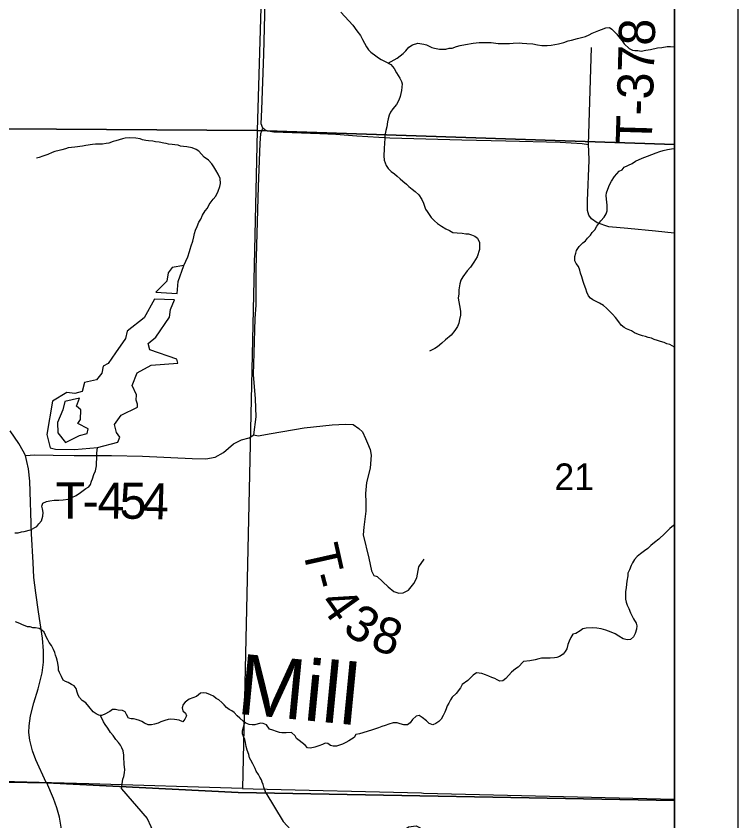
# Model space of a CAD drawing. Extents: x 0 to 34, y 0 to 22.
# Drawn here: x 29.781 to 30.917, y 17.785 to 19.051 of the extents above; entities that cross this region are included whole.
import ezdxf

# ---------------------------------------------------------------- set-up
doc = ezdxf.new("R2010")
doc.units = 0
for name, color, linetype in [('GM_X_Adjacent_County', 7, 'Continuous'), ('GM_X_County', 7, 'Continuous'), ('GM_X_County_Road', 7, 'Continuous'), ('GM_X_Minor_Lake', 7, 'Continuous'), ('GM_X_Minor_River', 7, 'Continuous'), ('GM_X_Minor_River_Text', 7, 'Continuous'), ('GM_X_Section', 7, 'Continuous'), ('GM_X_Section_Text', 7, 'Continuous'), ('GM_X_State_Route', 7, 'Continuous'), ('GM_X_Township', 7, 'Continuous'), ('GM_X_Township_Road', 7, 'Continuous'), ('GM_X_Township_Road_Text', 7, 'Continuous'), ('SH_Data', 7, 'Continuous')]:
    doc.layers.add(name, color=color, linetype=linetype)

msp = doc.modelspace()

# ---------------------------------------------------------------- linework, layer by layer
at = {"layer": 'GM_X_Adjacent_County'}
for points in [[(30.8167, 17.8174), (30.8167, 20.9), (24.0167, 20.9), (24.0167, 18.0693)], [(24.0167, 18.0693), (24.0167, 14.1), (30.8167, 14.1), (30.8167, 17.8174)], [(30.8167, 17.8174), (30.1304, 17.8301), (29.8296, 17.8449), (29.1279, 17.8574), (28.6324, 17.8677)], [(28.6324, 17.8677), (29.1279, 17.8574), (29.8296, 17.8449), (30.1304, 17.8301), (30.8167, 17.8174)]]:
    msp.add_lwpolyline(points, dxfattribs=at)
at = {"layer": 'GM_X_County'}
for points in [[(30.8167, 17.8174), (30.8167, 20.9), (24.0167, 20.9), (24.0167, 18.0693)], [(24.0167, 18.0693), (24.0167, 14.1), (30.8167, 14.1), (30.8167, 17.8174)], [(28.6324, 17.8677), (29.1279, 17.8574), (29.8296, 17.8449), (30.1304, 17.8301), (30.8167, 17.8174)], [(30.8167, 17.8174), (30.1304, 17.8301), (29.8296, 17.8449), (29.1279, 17.8574), (28.6324, 17.8677)]]:
    msp.add_lwpolyline(points, dxfattribs=at)
at = {"layer": 'GM_X_County_Road'}
for points in [[(30.1693, 18.8745), (30.167, 18.8813), (30.1678, 18.9036), (30.1709, 18.9907), (30.1749, 19.1352), (30.1785, 19.2629), (30.1788, 19.2864), (30.1782, 19.3154), (30.1794, 19.3235), (30.1825, 19.3315), (30.1887, 19.3469)], [(30.8167, 18.7092), (30.8162, 18.7094), (30.7869, 18.7126), (30.7433, 18.7167), (30.7139, 18.7195), (30.6955, 18.7258), (30.6866, 18.7321), (30.6823, 18.7377), (30.6803, 18.7451), (30.6803, 18.7603), (30.6825, 18.8243), (30.6823, 18.8382), (30.6818, 18.8484), (30.6719, 18.8496), (30.637, 18.8519), (30.5516, 18.8539), (30.4823, 18.8557), (30.3691, 18.8587), (30.3172, 18.862), (30.2842, 18.8646), (30.2589, 18.8656), (30.1865, 18.8681), (30.1746, 18.8704), (30.1693, 18.8745)]]:
    msp.add_lwpolyline(points, dxfattribs=at)
at = {"layer": 'GM_X_Minor_Lake'}
for points in [[(30.0453, 18.6586), (30.0268, 18.6555), (30.0204, 18.6472), (30.0185, 18.6339), (30.0011, 18.6168), (30.0345, 18.6146)], [(30.0345, 18.6146), (30.0363, 18.6332), (30.0453, 18.6586)], [(29.9989, 18.6058), (29.9827, 18.5762), (29.9558, 18.5552), (29.9536, 18.5435), (29.9378, 18.5214), (29.9261, 18.5043), (29.9181, 18.5005), (29.9162, 18.4891), (29.9076, 18.4789), (29.889, 18.4747), (29.8853, 18.4606), (29.8735, 18.4572), (29.861, 18.4591), (29.8387, 18.445), (29.8298, 18.393), (29.8347, 18.3721), (29.8435, 18.3695), (29.873, 18.3692), (29.9094, 18.3723)], [(29.9094, 18.3723), (29.9416, 18.3807), (29.9446, 18.3887), (29.9393, 18.3959), (29.9362, 18.4088), (29.9468, 18.4232), (29.9721, 18.4358), (29.9725, 18.4403), (29.9702, 18.4468), (29.9705, 18.4551), (29.9637, 18.4699), (29.9719, 18.4896), (29.9939, 18.5018), (30.0359, 18.505), (30.0344, 18.5114), (29.9919, 18.5257), (29.9892, 18.536), (30.0013, 18.5458), (30.0228, 18.5774), (30.024, 18.5891), (30.0307, 18.6047), (29.9989, 18.6058)], [(29.8811, 18.45), (29.858, 18.4446), (29.855, 18.4314), (29.8467, 18.4116), (29.8472, 18.3953), (29.859, 18.3805)], [(29.859, 18.3805), (29.8813, 18.3912), (29.8934, 18.3946), (29.8945, 18.4019), (29.8786, 18.4102), (29.8824, 18.4166), (29.8831, 18.4314), (29.8762, 18.4375), (29.8811, 18.45)]]:
    msp.add_lwpolyline(points, dxfattribs=at)
at = {"layer": 'GM_X_Minor_River'}
for points in [[(30.292, 19.0569), (30.2984, 19.0501), (30.3045, 19.0433), (30.311, 19.0365), (30.3175, 19.0274), (30.3228, 19.0202), (30.3262, 19.0138), (30.3323, 19.0024), (30.3357, 18.9975), (30.3395, 18.9941), (30.3471, 18.9884), (30.3513, 18.985), (30.3555, 18.9824), (30.3597, 18.9805), (30.3638, 18.9782), (30.3707, 18.9748), (30.376, 18.9684), (30.3798, 18.9616), (30.3851, 18.9532), (30.3874, 18.9479), (30.3886, 18.9441), (30.3878, 18.9335), (30.3856, 18.924), (30.3833, 18.9183), (30.3796, 18.9115), (30.3739, 18.905)], [(30.3666, 18.9769), (30.3809, 18.9843), (30.3903, 18.9919), (30.3945, 18.9961), (30.399, 19.0018), (30.4047, 19.0056), (30.4134, 19.0083), (30.4225, 19.0064), (30.427, 19.0053), (30.4354, 19.0015), (30.4396, 19.0004), (30.4471, 18.9989), (30.4574, 18.9989), (30.4623, 19), (30.4672, 19.0004), (30.474, 19.0027), (30.4797, 19.0046), (30.488, 19.0062), (30.5005, 19.0081), (30.5096, 19.0089), (30.5286, 19.0089), (30.5396, 19.0078), (30.5574, 19.0078), (30.5631, 19.0082), (30.5729, 19.0086), (30.5775, 19.0082), (30.5847, 19.0075), (30.5941, 19.0068), (30.6017, 19.0053), (30.6085, 19.0045), (30.6169, 19.0045), (30.6229, 19.0049), (30.6343, 19.0068), (30.643, 19.0091), (30.6498, 19.0118), (30.6551, 19.0129), (30.6646, 19.0156), (30.6767, 19.0187), (30.6828, 19.0213), (30.6873, 19.0236), (30.6979, 19.0282), (30.7021, 19.0297), (30.7089, 19.0324), (30.7146, 19.0328), (30.7184, 19.0301), (30.7222, 19.0267), (30.7263, 19.0222), (30.7286, 19.0184), (30.7347, 19.0116), (30.7378, 19.0071), (30.7457, 18.9995), (30.7507, 18.9972), (30.7545, 18.9965), (30.7594, 18.9965), (30.7647, 18.9957), (30.7719, 18.9973), (30.7791, 18.9984), (30.7901, 19.0007), (30.7969, 19.0015), (30.8056, 19.0026), (30.8105, 19.0027), (30.8167, 19.0023)], [(30.3739, 18.905), (30.3705, 18.8997), (30.3683, 18.8948), (30.3668, 18.8891), (30.3656, 18.8842), (30.3645, 18.8766), (30.363, 18.8709), (30.3615, 18.8629), (30.3612, 18.8576), (30.3608, 18.8515), (30.3601, 18.8417), (30.3597, 18.8307), (30.3605, 18.8239), (30.3617, 18.8201), (30.3636, 18.8155), (30.3666, 18.811), (30.3712, 18.8064), (30.3765, 18.8027), (30.3807, 18.7989), (30.3852, 18.7947), (30.3898, 18.7909), (30.3955, 18.7864), (30.3993, 18.7826), (30.4042, 18.7788), (30.4092, 18.7747), (30.4149, 18.7694), (30.4194, 18.7622), (30.4221, 18.7565), (30.4236, 18.7516), (30.4255, 18.747), (30.4278, 18.7432), (30.4343, 18.7338), (30.4396, 18.7288), (30.4442, 18.7247), (30.4502, 18.7205), (30.4571, 18.7164), (30.4631, 18.7133), (30.4685, 18.7103), (30.4753, 18.7099), (30.4829, 18.7092), (30.4889, 18.7085), (30.4931, 18.7081), (30.4977, 18.7066), (30.503, 18.7047), (30.5071, 18.7013), (30.5102, 18.6948), (30.5102, 18.6835), (30.5065, 18.6721), (30.5012, 18.6637), (30.4963, 18.6561), (30.4906, 18.6504), (30.4838, 18.6406), (30.4808, 18.6356), (30.4793, 18.6295), (30.4778, 18.6201), (30.4775, 18.614), (30.4767, 18.6072), (30.4787, 18.5954), (30.4806, 18.5867), (30.4802, 18.5806), (30.4787, 18.5738), (30.4776, 18.5681), (30.4757, 18.5624), (30.4716, 18.5563), (30.4655, 18.5491), (30.4568, 18.5419), (30.4508, 18.5366), (30.4444, 18.5308), (30.4398, 18.5278), (30.4315, 18.5236)], [(30.0453, 18.6586), (30.0517, 18.6723), (30.054, 18.6806), (30.0551, 18.6844), (30.0566, 18.6893), (30.0592, 18.6969), (30.0611, 18.7038), (30.0622, 18.7087), (30.0637, 18.714), (30.0664, 18.7201), (30.0686, 18.7265), (30.0717, 18.7315), (30.0743, 18.7379), (30.0788, 18.7444), (30.0822, 18.7489), (30.0852, 18.7543), (30.0882, 18.7584), (30.0913, 18.763), (30.0954, 18.7676), (30.0992, 18.7755), (30.1018, 18.7827), (30.1026, 18.7873), (30.1022, 18.7953), (30.0991, 18.8021), (30.0957, 18.8085), (30.0922, 18.8138), (30.0892, 18.8184), (30.0839, 18.824), (30.077, 18.829), (30.0729, 18.8335), (30.0687, 18.8384), (30.0645, 18.8411), (30.0581, 18.8437), (30.0501, 18.8452), (30.0444, 18.8456), (30.0402, 18.8463), (30.0364, 18.8478), (30.0308, 18.8482), (30.0266, 18.8489), (30.0213, 18.8493), (30.0175, 18.8504), (30.0137, 18.8508), (30.0065, 18.8523), (30.0004, 18.8531), (29.9966, 18.8538), (29.9894, 18.8546), (29.9853, 18.8553), (29.9803, 18.8561), (29.9765, 18.8576), (29.9697, 18.8587), (29.9602, 18.859), (29.953, 18.8586), (29.9489, 18.8575), (29.9383, 18.8544), (29.9341, 18.8537), (29.9273, 18.851), (29.9231, 18.8506), (29.9171, 18.8495), (29.9061, 18.8491), (29.9015, 18.8487), (29.8909, 18.8471), (29.8856, 18.8464), (29.8735, 18.8444), (29.8633, 18.8433), (29.8591, 18.8421), (29.8534, 18.8402), (29.8493, 18.8395), (29.8421, 18.8376), (29.8379, 18.836), (29.8315, 18.833), (29.8232, 18.8303), (29.8179, 18.8284), (29.8137, 18.8273)], [(30.7176, 18.7909), (30.7228, 18.7984), (30.73, 18.8068), (30.7346, 18.8091), (30.738, 18.8129), (30.7504, 18.819), (30.7557, 18.8228), (30.7663, 18.8274), (30.7747, 18.8304), (30.7883, 18.8358), (30.794, 18.8377), (30.7993, 18.8396), (30.8061, 18.8411), (30.8121, 18.8422), (30.8167, 18.8423)], [(30.8167, 18.53), (30.8134, 18.532), (30.8096, 18.5343), (30.8047, 18.5354), (30.8005, 18.5377), (30.7949, 18.5388), (30.7903, 18.5407), (30.785, 18.5422), (30.7808, 18.5441), (30.7755, 18.5452), (30.7713, 18.5467), (30.7664, 18.5482), (30.7603, 18.5501), (30.7539, 18.5527), (30.7493, 18.5558), (30.7414, 18.5588), (30.7376, 18.561), (30.733, 18.5648), (30.7292, 18.5698), (30.7243, 18.5766), (30.7193, 18.5822), (30.7102, 18.5913), (30.7053, 18.5959), (30.6988, 18.5993), (30.6939, 18.6019), (30.6886, 18.6046), (30.6848, 18.6072), (30.6817, 18.611), (30.679, 18.6167), (30.6775, 18.622), (30.6748, 18.6284), (30.6733, 18.6334), (30.6714, 18.6406), (30.6691, 18.6466), (30.668, 18.6512), (30.6657, 18.6572), (30.6622, 18.6618), (30.6603, 18.666), (30.6603, 18.6728), (30.6618, 18.6777), (30.6629, 18.6823), (30.6671, 18.6883), (30.6728, 18.694), (30.6769, 18.6975), (30.6803, 18.7016), (30.6848, 18.7062), (30.6875, 18.7104), (30.6916, 18.7146), (30.6947, 18.7203), (30.7011, 18.7286), (30.7064, 18.7347), (30.7094, 18.74), (30.7109, 18.7446), (30.7112, 18.7533), (30.7101, 18.7628), (30.7093, 18.7685), (30.71, 18.773), (30.7119, 18.7783), (30.7145, 18.7852), (30.7176, 18.7909)], [(29.7794, 18.2381), (29.7847, 18.2381), (29.7897, 18.2396), (29.7942, 18.2404), (29.804, 18.2431), (29.8139, 18.2484), (29.8169, 18.2522), (29.8211, 18.2572), (29.8233, 18.2644), (29.8237, 18.2701), (29.8229, 18.2761), (29.8217, 18.2803), (29.8236, 18.2849), (29.8293, 18.2875), (29.8342, 18.2887), (29.8414, 18.2895), (29.8486, 18.2895), (29.8554, 18.2902), (29.863, 18.2914), (29.8691, 18.2937), (29.8759, 18.2971), (29.8827, 18.3017), (29.891, 18.3078), (29.8955, 18.3104), (29.8982, 18.3142), (29.9001, 18.3192), (29.9016, 18.323), (29.9038, 18.3298), (29.9061, 18.3359), (29.9076, 18.3438), (29.9079, 18.3488), (29.9083, 18.3548), (29.9083, 18.3636), (29.9094, 18.3723), (29.9094, 18.3723)], [(30.8167, 18.2507), (30.8154, 18.2498), (30.8094, 18.2448), (30.8018, 18.2372), (30.7924, 18.2285), (30.7855, 18.2228), (30.7795, 18.2182), (30.775, 18.2136), (30.77, 18.2098), (30.7636, 18.2053)], [(30.7636, 18.2053), (30.7583, 18.2011), (30.7538, 18.1961), (30.7508, 18.1912), (30.7489, 18.1866), (30.7463, 18.1802), (30.7436, 18.1749), (30.7433, 18.1707), (30.7418, 18.1623), (30.741, 18.1525), (30.7399, 18.1453), (30.7396, 18.1396), (30.7396, 18.1339), (30.7407, 18.1293), (30.7426, 18.1244), (30.7449, 18.1191), (30.7476, 18.1123), (30.7499, 18.1085), (30.7522, 18.1028), (30.7564, 18.096), (30.7575, 18.0918), (30.7571, 18.0869), (30.7553, 18.0797), (30.7526, 18.0747), (30.7477, 18.0705), (30.7424, 18.0698), (30.7363, 18.0717), (30.7295, 18.0758), (30.7234, 18.0792), (30.7174, 18.0822), (30.709, 18.0853), (30.7014, 18.0875), (30.695, 18.0883), (30.6874, 18.089), (30.6779, 18.0882), (30.673, 18.0871), (30.6685, 18.084), (30.6617, 18.0802), (30.6571, 18.0787), (30.6537, 18.0734), (30.6511, 18.0681), (30.6492, 18.0624), (30.6477, 18.0559), (30.6451, 18.0514), (30.6417, 18.0472), (30.636, 18.0438), (30.6318, 18.0422), (30.6281, 18.0418), (30.6212, 18.0414), (30.6137, 18.041), (30.608, 18.041), (30.6038, 18.0403), (30.5977, 18.0387), (30.5894, 18.0372), (30.5796, 18.0357), (30.5713, 18.0269), (30.5671, 18.0243), (30.5607, 18.0193), (30.5516, 18.0094), (30.5471, 18.0056), (30.5421, 18.0052), (30.538, 18.0071), (30.5342, 18.009), (30.5296, 18.0109), (30.5247, 18.0128), (30.5198, 18.0151), (30.5137, 18.0169), (30.5057, 18.0181), (30.5004, 18.0146), (30.4921, 18.0059), (30.483, 17.9998), (30.4804, 17.9945), (30.4736, 17.9854), (30.4672, 17.98), (30.4645, 17.9755), (30.4619, 17.9702), (30.4593, 17.966), (30.4578, 17.9614), (30.4555, 17.9561), (30.4532, 17.9512), (30.4499, 17.9455), (30.4461, 17.9417), (30.4415, 17.9386), (30.4366, 17.9363), (30.4313, 17.9382), (30.4267, 17.9428), (30.4203, 17.9477), (30.4154, 17.9511), (30.4108, 17.95), (30.4051, 17.9446), (30.401, 17.9397), (30.3968, 17.9363), (30.3911, 17.9366), (30.3855, 17.9381), (30.3805, 17.9393), (30.3745, 17.9393), (30.3676, 17.9373), (30.362, 17.9351), (30.3567, 17.9335), (30.3514, 17.9316), (30.3404, 17.9278)], [(29.8684, 18), (29.8635, 18.0031), (29.8593, 18.0046), (29.8555, 18.0065), (29.8528, 18.0121), (29.8498, 18.0186), (29.8483, 18.0224), (29.8482, 18.0266), (29.8471, 18.0334), (29.8459, 18.0379), (29.8448, 18.0417), (29.8433, 18.0459), (29.8421, 18.0501), (29.8402, 18.0546), (29.8372, 18.0611), (29.8334, 18.066), (29.8315, 18.0698), (29.8292, 18.0736), (29.8276, 18.0774), (29.8254, 18.0819), (29.8216, 18.0853), (29.8178, 18.088), (29.8117, 18.0887), (29.8079, 18.0887), (29.8037, 18.0902), (29.7992, 18.0902), (29.7954, 18.0921), (29.7912, 18.0936), (29.7874, 18.0959), (29.7806, 18.0981)], [(30.3404, 17.9278), (30.3215, 17.9224), (30.3158, 17.9213), (30.3131, 17.9164), (30.3048, 17.9114), (30.2999, 17.9084), (30.295, 17.9061), (30.2901, 17.9042), (30.2851, 17.9026), (30.2798, 17.9026), (30.276, 17.9038), (30.2715, 17.9072), (30.2673, 17.9075), (30.2632, 17.9056), (30.2575, 17.9033), (30.251, 17.9014), (30.2442, 17.8995), (30.2397, 17.9003), (30.2359, 17.9044), (30.2313, 17.9078), (30.2264, 17.9116), (30.2222, 17.9147), (30.2203, 17.9192), (30.2146, 17.9241), (30.2059, 17.9237), (30.1994, 17.9237), (30.1956, 17.9241), (30.1907, 17.926), (30.185, 17.9279), (30.1801, 17.9297), (30.1752, 17.9362), (30.1698, 17.9384), (30.1657, 17.9392), (30.1566, 17.9365), (30.1528, 17.9365), (30.1482, 17.9369), (30.1426, 17.9391), (30.1384, 17.9422), (30.1331, 17.9467), (30.1293, 17.9505), (30.1243, 17.9558), (30.1205, 17.9581), (30.1163, 17.9607), (30.1122, 17.9637), (30.1087, 17.9679), (30.1049, 17.9713), (30.1, 17.9755), (30.0962, 17.9778), (30.0917, 17.9812), (30.0871, 17.9834), (30.0807, 17.9861), (30.0765, 17.9864), (30.0712, 17.986), (30.0651, 17.9811), (30.0538, 17.9765), (30.0473, 17.972), (30.0443, 17.9682), (30.0428, 17.9632), (30.0436, 17.9583), (30.0478, 17.9545), (30.0493, 17.9507), (30.0467, 17.945), (30.0436, 17.9412), (30.038, 17.9435), (30.0304, 17.9446), (30.0243, 17.945), (30.0205, 17.9446), (30.0152, 17.9431), (30.0092, 17.9411), (30.005, 17.9392), (29.9993, 17.9373), (29.9944, 17.9366), (29.9891, 17.9366), (29.9834, 17.9392), (29.9792, 17.9418), (29.9754, 17.9434), (29.9701, 17.9449), (29.966, 17.9456), (29.9622, 17.9456), (29.9584, 17.9467), (29.9549, 17.9528), (29.953, 17.9566), (29.9485, 17.9589), (29.942, 17.9596), (29.9375, 17.9604), (29.9329, 17.9603), (29.9288, 17.9573), (29.9201, 17.9527), (29.9155, 17.9512), (29.9117, 17.9516), (29.9072, 17.9538), (29.9026, 17.9569), (29.8958, 17.9652), (29.8909, 17.9709), (29.8855, 17.9747), (29.881, 17.9792), (29.8791, 17.983), (29.8775, 17.9875), (29.8756, 17.9936), (29.8726, 17.9978), (29.8684, 18)], [(29.9472, 17.8355), (29.9492, 17.8507), (29.9507, 17.8553), (29.9518, 17.861), (29.9522, 17.8663), (29.9514, 17.8739), (29.9514, 17.878), (29.951, 17.8826), (29.951, 17.8887), (29.9498, 17.8955), (29.9475, 17.9), (29.9456, 17.9042), (29.9426, 17.9084), (29.9384, 17.9133), (29.9342, 17.9197), (29.93, 17.9243), (29.9254, 17.9311), (29.9213, 17.9368), (29.919, 17.9413), (29.9163, 17.947), (29.9137, 17.9514)], [(30.1743, 17.8295), (30.1709, 17.8383), (30.1697, 17.8425), (30.1682, 17.8462), (30.1671, 17.85), (30.1648, 17.8538), (30.1625, 17.8584), (30.1591, 17.8637), (30.1575, 17.8675), (30.1537, 17.8751), (30.1507, 17.8807), (30.1484, 17.8845), (30.1472, 17.8895), (30.1446, 17.8963), (30.143, 17.9023), (30.1423, 17.9084), (30.1411, 17.9133), (30.1392, 17.9179), (30.1377, 17.9221), (30.1377, 17.927), (30.1409, 17.9403)], [(29.9472, 17.8355), (29.9875, 17.7892), (30.0104, 17.7388), (30.0131, 17.7138), (30.0118, 17.6732), (30.0191, 17.6459), (30.0245, 17.6239), (30.0348, 17.6118), (30.0564, 17.5986), (30.082, 17.5554), (30.0915, 17.5452), (30.1347, 17.5196), (30.1564, 17.4972), (30.1659, 17.4867), (30.1762, 17.4806), (30.1963, 17.4765), (30.2039, 17.4602)], [(30.1743, 17.8295), (30.2014, 17.7846), (30.22, 17.7642), (30.2962, 17.7489), (30.3344, 17.7456), (30.3586, 17.7441), (30.3696, 17.748), (30.3884, 17.7693), (30.3986, 17.7758), (30.4104, 17.7773), (30.4248, 17.7702), (30.45, 17.7232), (30.4735, 17.696), (30.4884, 17.6873), (30.5554, 17.6712), (30.5883, 17.6751), (30.6005, 17.6729), (30.6376, 17.6563), (30.6657, 17.6538), (30.677, 17.6492), (30.6869, 17.6462), (30.6967, 17.6444)]]:
    msp.add_lwpolyline(points, dxfattribs=at)
at = {"layer": 'GM_X_Section'}
for p, q in [((30.8167, 18.8488), (30.8167, 19.8701)), ((30.8167, 17.8197), (30.8167, 18.8488))]:
    msp.add_line(p, q, dxfattribs=at)
for points in [[(29.153, 19.9086), (30.191, 19.8901), (30.1607, 18.8706), (29.1334, 18.8778)], [(29.1334, 18.8778), (30.1607, 18.8706), (30.1377, 17.8362), (29.8958, 17.8434), (29.6223, 17.851), (29.3858, 17.8581), (29.1338, 17.8638)]]:
    msp.add_lwpolyline(points, close=True, dxfattribs=at)
for points in [[(30.8167, 19.8701), (30.191, 19.8901), (30.1607, 18.8706), (30.8167, 18.8488)], [(30.8167, 18.8488), (30.1607, 18.8706), (30.1377, 17.8362), (30.1543, 17.8357), (30.4189, 17.8292), (30.4222, 17.8291), (30.6646, 17.8229), (30.8167, 17.8197)]]:
    msp.add_lwpolyline(points, dxfattribs=at)
at = {"layer": 'GM_X_State_Route'}
for points in [[(29.8287, 17.8457), (29.8124, 17.8812), (29.8069, 17.8955), (29.8029, 17.912), (29.8014, 17.9245), (29.8019, 17.935), (29.8038, 17.9503), (29.8094, 17.9708), (29.8163, 17.9927), (29.8225, 18.0181), (29.8246, 18.0348), (29.8246, 18.0528), (29.823, 18.0727), (29.8165, 18.1138), (29.8122, 18.1437), (29.8093, 18.1679), (29.8081, 18.1918), (29.8055, 18.2366), (29.8031, 18.3197), (29.8007, 18.3388), (29.7985, 18.3503), (29.7959, 18.3596), (29.7923, 18.3666), (29.7859, 18.3785), (29.772, 18.3984)], [(29.8553, 17.68), (29.8557, 17.6886), (29.8556, 17.7322), (29.8551, 17.7432), (29.8541, 17.7609), (29.8523, 17.7756), (29.8494, 17.791), (29.8453, 17.806), (29.84, 17.8207), (29.8296, 17.8449)]]:
    msp.add_lwpolyline(points, dxfattribs=at)
at = {"layer": 'GM_X_Township'}
msp.add_line((30.8167, 15.629), (30.8167, 17.8174), dxfattribs=at)
for points in [[(30.8167, 17.8174), (30.8167, 20.9), (26.3564, 20.9)], [(30.8167, 17.8174), (30.1304, 17.8301), (29.8296, 17.8449), (29.1279, 17.8574), (28.6324, 17.8677), (28.1264, 17.8728), (27.8903, 17.8826), (27.7531, 17.8783), (27.1422, 17.8906), (26.9072, 17.9017), (26.4988, 17.9198), (26.3979, 17.9244), (26.2521, 17.9299), (26.228, 17.2045)], [(28.6324, 17.8677), (29.1279, 17.8574), (29.8296, 17.8449), (30.1304, 17.8301), (30.8167, 17.8174)]]:
    msp.add_lwpolyline(points, dxfattribs=at)
at = {"layer": 'GM_X_Township_Road'}
for points in [[(30.6818, 18.8484), (30.685, 18.9502), (30.6865, 19.0012)], [(30.1554, 18.3921), (30.1592, 18.4204), (30.1581, 18.4491), (30.1549, 18.487), (30.1556, 18.5205), (30.1574, 18.5752), (30.1588, 18.5964), (30.1592, 18.6534), (30.1627, 18.783), (30.1655, 18.8506), (30.1665, 18.8663), (30.1693, 18.8745)], [(30.1554, 18.3921), (30.1622, 18.3908), (30.1825, 18.3944), (30.2346, 18.4035), (30.2784, 18.4078), (30.2992, 18.4093), (30.3116, 18.4083), (30.3205, 18.4025), (30.326, 18.3969), (30.3311, 18.3865), (30.3339, 18.3794), (30.3382, 18.3693), (30.34, 18.3604), (30.3384, 18.3399), (30.3326, 18.3171), (30.3311, 18.3002), (30.3316, 18.2857), (30.3316, 18.2723), (30.3283, 18.247), (30.3275, 18.2351), (30.3359, 18.1984), (30.3405, 18.1786), (30.3438, 18.171), (30.3493, 18.1695), (30.3668, 18.1533), (30.3757, 18.146), (30.3833, 18.1434), (30.3901, 18.1439), (30.3984, 18.1482), (30.4068, 18.1586), (30.4114, 18.1677), (30.4146, 18.1845), (30.423, 18.1966)], [(29.7959, 18.3596), (29.8108, 18.3608), (29.8395, 18.3601), (29.8725, 18.3596), (29.9314, 18.3596), (29.98, 18.3589), (30.0581, 18.3551), (30.0799, 18.3544), (30.0943, 18.3571), (30.1078, 18.3645), (30.1234, 18.3779), (30.1361, 18.3842), (30.1478, 18.3878), (30.1554, 18.3921)]]:
    msp.add_lwpolyline(points, dxfattribs=at)
at = {"layer": 'SH_Data'}
for points in [[(23.9167, 21), (30.9167, 21), (30.9167, 14), (23.9167, 14)], [(24.0167, 20.9), (30.8167, 20.9), (30.8167, 14.1), (24.0167, 14.1)]]:
    msp.add_lwpolyline(points, close=True, dxfattribs=at)

# ---------------------------------------------------------------- texts
at = {"layer": 'GM_X_Minor_River_Text'}
msp.add_text('Mill', height=0.0947, rotation=354.4644, dxfattribs=at).set_placement((30.1268, 17.954))
at = {"layer": 'GM_X_Section_Text'}
msp.add_text('21', height=0.04186, rotation=0, dxfattribs=at).set_placement((30.628, 18.3054))
at = {"layer": 'GM_X_Township_Road_Text'}
for s, height, rotation, p in [('T-378', 0.05682, 88.316, (30.7811, 18.8475)), ('T', 0.0568, 359.9957, (29.8434, 18.2606)), ('4', 0.0568, 359.8335, (29.9092, 18.2606)), ('5', 0.0568, 359.4692, (29.9441, 18.2605)), ('4', 0.0568, 358.2304, (29.9788, 18.2602)), ('-', 0.0568, 359.961, (29.8859, 18.2606)), ('T', 0.0568, 282.6329, (30.2313, 18.2138)), ('-', 0.0568, 284.7269, (30.2411, 18.1701)), ('4', 0.0568, 305.4012, (30.2564, 18.1274)), ('3', 0.0568, 326.3065, (30.2928, 18.0832)), ('8', 0.0568, 341.3364, (30.3365, 18.0567))]:
    msp.add_text(s, height=height, rotation=rotation, dxfattribs=at).set_placement(p)

doc.saveas('drawing.dxf')
